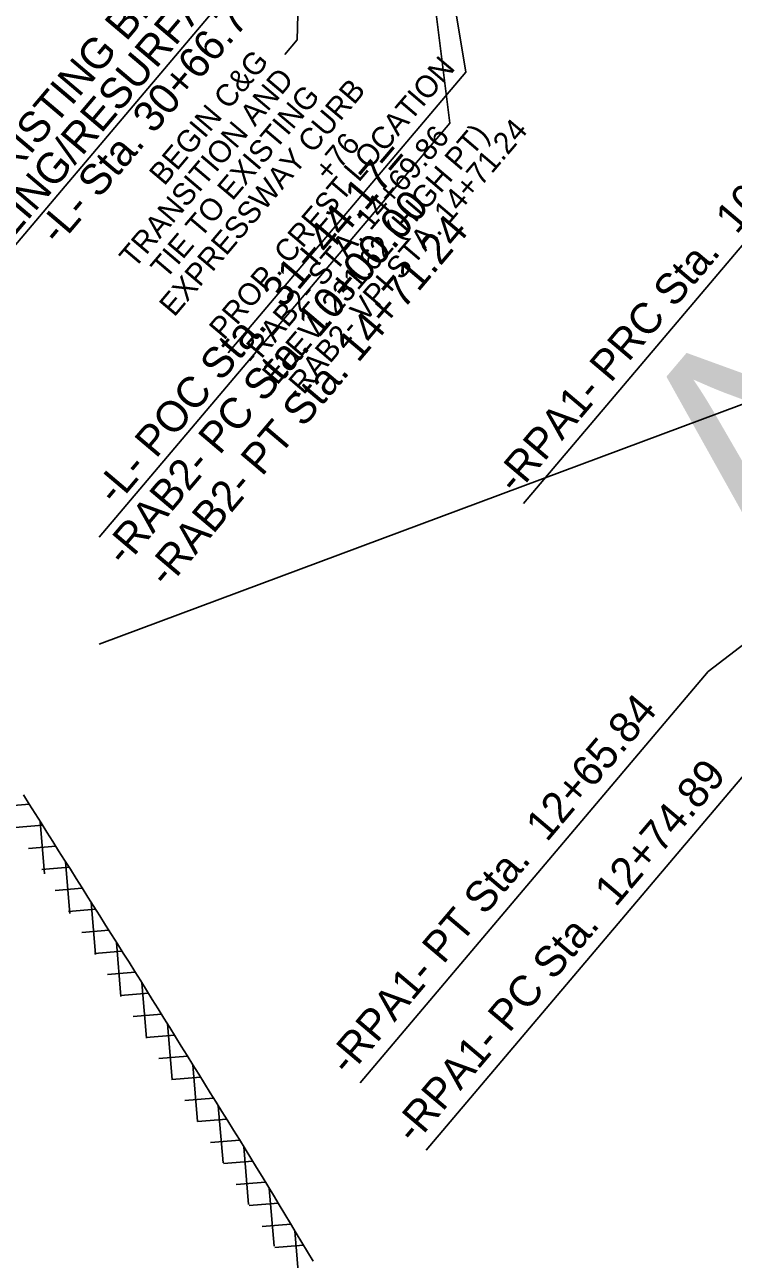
# Model space of a CAD drawing. Extents: x 1761082 to 1764358, y 421907 to 425434.
# Drawn here: x 1762604.1 to 1762765.1, y 423126 to 423406.5 of the extents above; entities that cross this region are included whole.
import ezdxf

# ---------------------------------------------------------------- set-up
doc = ezdxf.new("R2010")
doc.units = 0
for name, color, linetype in [('MARK UTURN ARROW CELL', 7, 'Continuous'), ('Prop Conc 4in Sidewalk', 7, 'Continuous'), ('Prop Mkg Solid White Stop Bar', 7, 'Continuous'), ('Prop Mkg Solid Yel Skip LT', 7, 'Continuous'), ('Prop Mkg Solid Yel Skip RT', 7, 'Continuous'), ('Prop Mkr CR 80ft Spc', 7, 'Continuous'), ('Scratch_Level_1', 7, 'Continuous')]:
    doc.layers.add(name, color=color, linetype=linetype)

msp = doc.modelspace()

# ---------------------------------------------------------------- linework, layer by layer
at = {"layer": 'MARK UTURN ARROW CELL'}
for points in [[(1762680.61, 423545.38), (1762700.7, 423384.1), (1762621.03, 423290.05)], [(1762815.42, 423516.34), (1762800.3, 423395.47), (1762717.5, 423297.73)], [(1762572.31, 423321.5), (1762658.86, 423423.66), (1762630.42, 423487.69)], [(1762901.44, 423368.33), (1762759.45, 423259.49), (1762680.33, 423166.09)], [(1762904.67, 423359.77), (1762774.23, 423243.86), (1762695.38, 423150.78)]]:
    msp.add_lwpolyline(points, dxfattribs=at)
at = {"layer": 'Prop Conc 4in Sidewalk'}
for p, q in [((1762605.18, 423229.35), (1762598.94, 423228.84)), ((1762608.19, 423224.58), (1762601.97, 423224.07)), ((1762608.64, 423213.58), (1762607.66, 423225.44)), ((1762611.2, 423219.82), (1762605, 423219.3)), ((1762614.4, 423204.5), (1762613.43, 423216.28)), ((1762614.21, 423215.05), (1762608.03, 423214.54)), ((1762617.22, 423210.28), (1762611.06, 423209.77)), ((1762620.19, 423195.18), (1762619.2, 423207.13)), ((1762620.23, 423205.51), (1762614.09, 423205)), ((1762623.24, 423200.74), (1762617.08, 423200.23)), ((1762626.24, 423195.97), (1762620.02, 423195.46)), ((1762625.99, 423185.71), (1762624.98, 423197.98)), ((1762629.25, 423191.21), (1762622.95, 423190.68)), ((1762631.79, 423176.23), (1762630.75, 423188.81)), ((1762632.24, 423186.44), (1762625.87, 423185.91)), ((1762635.2, 423181.66), (1762628.79, 423181.13)), ((1762637.6, 423166.76), (1762636.54, 423179.51)), ((1762638.16, 423176.89), (1762631.72, 423176.36)), ((1762641.13, 423172.12), (1762634.64, 423171.58)), ((1762643.4, 423157.29), (1762642.33, 423170.18)), ((1762644.09, 423167.35), (1762637.57, 423166.81)), ((1762647.05, 423162.58), (1762640.49, 423162.03)), ((1762649.2, 423147.84), (1762648.12, 423160.86)), ((1762650.02, 423157.81), (1762643.42, 423157.26)), ((1762652.98, 423153.03), (1762646.35, 423152.48)), ((1762654.99, 423138.39), (1762653.91, 423151.54)), ((1762655.94, 423148.26), (1762649.28, 423147.71)), ((1762658.85, 423143.48), (1762652.21, 423142.94)), ((1762660.79, 423128.95), (1762659.71, 423142.06)), ((1762661.73, 423138.71), (1762655.14, 423138.16)), ((1762664.61, 423133.93), (1762658.07, 423133.39)), ((1762666.59, 423119.51), (1762665.52, 423132.4)), ((1762667.48, 423129.15), (1762661, 423128.61))]:
    msp.add_line(p, q, dxfattribs=at)
at = {"layer": 'Prop Mkg Solid White Stop Bar'}
msp.add_lwpolyline([(1762603.84, 423231.48), (1762605.17, 423229.37), (1762606.51, 423227.25), (1762607.84, 423225.14), (1762609.17, 423223.03), (1762610.51, 423220.91), (1762611.84, 423218.8), (1762613.18, 423216.69), (1762614.51, 423214.57), (1762615.84, 423212.46), (1762617.18, 423210.34), (1762618.51, 423208.23), (1762619.85, 423206.12), (1762621.18, 423204), (1762622.51, 423201.89), (1762623.85, 423199.77), (1762625.18, 423197.66), (1762626.52, 423195.55), (1762627.85, 423193.44), (1762629.17, 423191.33), (1762630.49, 423189.23), (1762631.81, 423187.13), (1762633.12, 423185.01), (1762634.44, 423182.89), (1762635.75, 423180.77), (1762637.07, 423178.65), (1762638.39, 423176.52), (1762639.71, 423174.4), (1762641.03, 423172.28), (1762642.35, 423170.15), (1762643.67, 423168.03), (1762644.99, 423165.91), (1762646.3, 423163.78), (1762647.62, 423161.66), (1762648.94, 423159.54), (1762650.26, 423157.41), (1762651.58, 423155.29), (1762652.9, 423153.17), (1762654.21, 423151.05), (1762655.52, 423148.94), (1762656.81, 423146.84), (1762658.09, 423144.74), (1762659.37, 423142.62), (1762660.66, 423140.49), (1762661.95, 423138.35), (1762663.23, 423136.21), (1762664.52, 423134.07), (1762665.81, 423131.92), (1762667.1, 423129.78), (1762668.39, 423127.64), (1762669.68, 423125.5)], dxfattribs=at)
at = {"layer": 'Prop Mkg Solid Yel Skip RT'}
msp.add_lwpolyline([(1762667.77, 423468.24), (1762666.05, 423403.09), (1762663.21, 423399.74)], dxfattribs=at)
at = {"layer": 'Prop Mkr CR 80ft Spc'}
msp.add_line((1762621.04, 423265.75), (1762902.15, 423370.52), dxfattribs=at)
at = {"layer": 'Scratch_Level_1'}
msp.add_lwpolyline([(1762679.14, 423547.37), (1762704.35, 423395.7), (1762650.35, 423331.96)], dxfattribs=at)

# ---------------------------------------------------------------- texts
at = {"layer": 'MARK UTURN ARROW CELL'}
for s, p in [('BEGIN MILLING/RESURFACING', (1762570.73, 423321.7)), ('END EXISTING BRIDGE', (1762582.78, 423350.13)), ('-L- Sta. 30+66.70', (1762611.88, 423356.09)), ('-RPA1- PRC Sta.  10+92.78', (1762715.76, 423299.52)), ('-L- POC Sta.  31+44.17=', (1762624.87, 423297.03)), ('-RAB2- PC Sta. 10+00.00', (1762626.86, 423283.13)), ('-RAB2- PT Sta. 14+71.24', (1762636.51, 423278.28)), ('-RPA1- PT Sta.  12+65.84', (1762677.71, 423167.4)), ('-RPA1- PC Sta.  12+74.89', (1762692.67, 423151.82))]:
    msp.add_text(s, height=7, rotation=49.7301, dxfattribs=at).set_placement(p)
at = {"layer": 'Prop Mkg Solid Yel Skip LT'}
for s, height, p in [('BEGIN C&G', 5, (1762635.82, 423369.7)), ('TRANSITION AND', 5, (1762629.05, 423350.87)), ('TIE TO EXISTING', 5, (1762636.17, 423348.45)), ('EXPRESSWAY CURB', 5, (1762638.1, 423339.9)), ('+76', 5, (1762673.28, 423370.59)), ('A', 50, (1762775.88, 423279.78))]:
    msp.add_text(s, height=height, rotation=49.7301, dxfattribs=at).set_placement(p)
at = {"layer": 'Scratch_Level_1'}
for s, p in [('PROP. CREST LOCATION', (1762649.42, 423334.62)), ('-RAB2- VPI STA. 14+71.24', (1762666.02, 423320.56)), ('-RAB2- STA. 14+69.86', (1762656.43, 423328.69)), ('ELEV. 231.62 (HIGH PT)', (1762661.47, 423324.42))]:
    msp.add_text(s, height=5, rotation=49.5644, dxfattribs=at).set_placement(p)

doc.saveas('drawing.dxf')
